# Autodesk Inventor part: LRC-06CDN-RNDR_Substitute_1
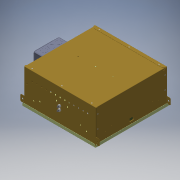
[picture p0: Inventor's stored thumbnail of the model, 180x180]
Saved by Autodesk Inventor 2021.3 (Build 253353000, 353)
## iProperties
Part Number: LRC-06CDN-RNDR_Substitute_1
Material: Generic
Document SubType Name: Modeling
Designer: JChurch
Manufacturer: Standard
Standards Organization: Custom
Density: 1 g/cm^3
Appearance: Smooth - Black
Author: JChurch
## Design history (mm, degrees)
derived "LRC-06CDN-RNDR.iam"
body "Solid9"
node "830399-00-00.ipt:1"
node "830455-00-38.ipt:1"
body "Solid10"
node "881088-00-00.iam:1::830140-00-00.ipt:1"
body "Solid11"
node "881088-00-00.iam:1::850014-00-00.iam:1::805044-00-00.ipt:1"
body "Solid12"
node "881088-00-00.iam:1::850014-00-00.iam:1::805174-00-00.ipt:1"
body "Solid13"
node "881088-00-00.iam:1::850014-00-00.iam:1::502055-00-00.ipt:1"
body "Solid14"
node "881088-00-00.iam:1::850014-00-00.iam:1::502055-00-00.ipt:2"
body "Solid15"
node "881088-00-00.iam:1::850014-00-00.iam:1::507032-00-00.ipt:1"
body "Solid16"
node "881088-00-00.iam:1::507000-00-00.ipt:1"
body "Solid17"
node "881088-00-00.iam:1::507000-00-00.ipt:2"
body "Solid18"
node "881088-00-00.iam:1::506002-00-00.ipt:1"
body "Solid19"
node "881088-00-00.iam:1::506002-00-00.ipt:2"
body "Solid20"
node "881088-00-00.iam:1::506002-00-00.ipt:3"
body "Solid21"
node "881088-00-00.iam:1::506002-00-00.ipt:4"
body "Solid22"
node "881088-00-00.iam:1::506002-00-00.ipt:5"
body "Solid23"
node "881088-00-00.iam:1::506002-00-00.ipt:6"
body "Solid24"
node "881088-00-00.iam:1::506002-00-00.ipt:7"
body "Solid25"
node "881088-00-00.iam:1::506002-00-00.ipt:8"
body "Solid26"
node "881088-00-00.iam:1::506002-00-00.ipt:9"
body "Solid27"
node "881088-00-00.iam:1::506002-00-00.ipt:10"
body "Solid28"
node "881088-00-00.iam:1::506002-00-00.ipt:11"
body "Solid29"
node "881088-00-00.iam:1::506002-00-00.ipt:12"
body "Solid30"
node "881088-00-00.iam:1::506002-00-00.ipt:13"
body "Solid31"
node "881088-00-00.iam:1::506002-00-00.ipt:14"
body "Solid32"
node "881088-00-00.iam:1::830392-01-00.iam:1::830392-00-00.ipt:1"
body "Solid33"
node "881088-00-00.iam:1::830392-01-00.iam:1::500027-00-00.ipt:1"
body "Solid34"
node "881088-00-00.iam:1::830392-01-00.iam:1::501030-00-00.ipt:1"
body "Solid35"
node "881088-00-00.iam:1::830392-01-00.iam:1::500027-00-00.ipt:2"
body "Solid36"
node "881088-00-00.iam:1::830392-01-00.iam:1::501030-00-00.ipt:2"
body "Solid37"
node "881088-00-00.iam:1::830392-01-00.iam:1::501030-00-00.ipt:3"
body "Solid38"
node "881088-00-00.iam:1::830392-01-00.iam:1::501030-00-00.ipt:4"
body "Solid39"
node "881088-00-00.iam:1::830392-01-00.iam:2::830392-00-00.ipt:1"
body "Solid40"
node "881088-00-00.iam:1::830392-01-00.iam:2::500027-00-00.ipt:1"
body "Solid41"
node "881088-00-00.iam:1::830392-01-00.iam:2::501030-00-00.ipt:1"
body "Solid42"
node "881088-00-00.iam:1::830392-01-00.iam:2::500027-00-00.ipt:2"
body "Solid43"
node "881088-00-00.iam:1::830392-01-00.iam:2::501030-00-00.ipt:2"
body "Solid44"
node "881088-00-00.iam:1::830392-01-00.iam:2::501030-00-00.ipt:3"
body "Solid45"
node "881088-00-00.iam:1::830392-01-00.iam:2::501030-00-00.ipt:4"
body "Solid46"
node "750043-00-XX.iam:1::700050-00-XX.ipt:1"
body "Solid47"
node "750043-00-XX.iam:1::507014-00-00.ipt:1"
body "Solid48"
node "750043-00-XX.iam:1::507014-00-00.ipt:2"
body "Solid49"
node "725075-00-00.ipt:1"
body "Solid50"
other parameters: "d15" = 61.595, "d16" = 9.525, "d17" = 9.525, "d35" = 5.08
